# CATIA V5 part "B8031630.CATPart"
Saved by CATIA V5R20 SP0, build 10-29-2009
Part number: B8031630
Revision: 12
Definition: design
Nomenclature: B8031630
Source: made
Description: NOT SPECIFIED
Bounding box of the stored display mesh (mm): x -14 to 14, y -14 to 14, z 0 to 30
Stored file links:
  C:\Users\Utente\Desktop\3D files B803\B8031630.CATPart
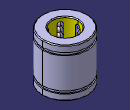
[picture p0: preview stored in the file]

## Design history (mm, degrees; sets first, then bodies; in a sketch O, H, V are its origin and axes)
Body1 "MANIFOLD_SOLID_BREP #38" (main body)
  Solid1: solid without history
Body2 "MANIFOLD_SOLID_BREP #76"
  Solid2: solid without history
Body3 "MANIFOLD_SOLID_BREP #114"
  Solid3: solid without history
Body4 "MANIFOLD_SOLID_BREP #152"
  Solid4: solid without history
Body5 "MANIFOLD_SOLID_BREP #190"
  Solid5: solid without history
Body6 "MANIFOLD_SOLID_BREP #228"
  Solid6: solid without history
Body7 "MANIFOLD_SOLID_BREP #266"
  Solid7: solid without history
Body8 "MANIFOLD_SOLID_BREP #304"
  Solid8: solid without history
Body9 "MANIFOLD_SOLID_BREP #2066"
  Solid9: solid without history
Body10 "MANIFOLD_SOLID_BREP #2104"
  Solid10: solid without history
Body11 "MANIFOLD_SOLID_BREP #2142"
  Solid11: solid without history
Body12 "MANIFOLD_SOLID_BREP #2180"
  Solid12: solid without history
Body13 "MANIFOLD_SOLID_BREP #2218"
  Solid13: solid without history
Body14 "MANIFOLD_SOLID_BREP #2256"
  Solid14: solid without history
Body15 "MANIFOLD_SOLID_BREP #2294"
  Solid15: solid without history
Body16 "MANIFOLD_SOLID_BREP #2332"
  Solid16: solid without history
Body17 "MANIFOLD_SOLID_BREP #2370"
  Solid17: solid without history
Body18 "MANIFOLD_SOLID_BREP #2408"
  Solid18: solid without history
Body19 "MANIFOLD_SOLID_BREP #2446"
  Solid19: solid without history
Body20 "MANIFOLD_SOLID_BREP #2484"
  Solid20: solid without history
Body21 "MANIFOLD_SOLID_BREP #2522"
  Solid21: solid without history
Body22 "MANIFOLD_SOLID_BREP #2560"
  Solid22: solid without history
Body23 "MANIFOLD_SOLID_BREP #2598"
  Solid23: solid without history
Body24 "MANIFOLD_SOLID_BREP #2636"
  Solid24: solid without history
Body25 "MANIFOLD_SOLID_BREP #2674"
  Solid25: solid without history
Body26 "MANIFOLD_SOLID_BREP #2712"
  Solid26: solid without history
Body27 "MANIFOLD_SOLID_BREP #2750"
  Solid27: solid without history
Body28 "MANIFOLD_SOLID_BREP #2788"
  Solid28: solid without history
Body29 "MANIFOLD_SOLID_BREP #2826"
  Solid29: solid without history
Body30 "MANIFOLD_SOLID_BREP #2864"
  Solid30: solid without history
Body31 "MANIFOLD_SOLID_BREP #2902"
  Solid31: solid without history
Body32 "MANIFOLD_SOLID_BREP #2940"
  Solid32: solid without history
Body33 "MANIFOLD_SOLID_BREP #2978"
  Solid33: solid without history
Body34 "MANIFOLD_SOLID_BREP #3016"
  Solid34: solid without history
Body35 "MANIFOLD_SOLID_BREP #3054"
  Solid35: solid without history
Body36 "MANIFOLD_SOLID_BREP #3092"
  Solid36: solid without history
Body37 "MANIFOLD_SOLID_BREP #3130"
  Solid37: solid without history
Body38 "MANIFOLD_SOLID_BREP #3168"
  Solid38: solid without history
Body39 "MANIFOLD_SOLID_BREP #3206"
  Solid39: solid without history
Body40 "MANIFOLD_SOLID_BREP #3244"
  Solid40: solid without history
Body41 "MANIFOLD_SOLID_BREP #3282"
  Solid41: solid without history
Body42 "MANIFOLD_SOLID_BREP #3320"
  Solid42: solid without history
Body43 "MANIFOLD_SOLID_BREP #3358"
  Solid43: solid without history
Body44 "MANIFOLD_SOLID_BREP #3396"
  Solid44: solid without history
Body45 "MANIFOLD_SOLID_BREP #3434"
  Solid45: solid without history
Body46 "MANIFOLD_SOLID_BREP #3472"
  Solid46: solid without history
Body47 "MANIFOLD_SOLID_BREP #3510"
  Solid47: solid without history
Body48 "MANIFOLD_SOLID_BREP #3548"
  Solid48: solid without history
Body49 "MANIFOLD_SOLID_BREP #3586"
  Solid49: solid without history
